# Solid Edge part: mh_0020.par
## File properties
Title: shaft
Author: edge
Template: normal.par
Last saved by: edge
Revision: 33
Application: Solid Edge
Material: SWM-B
非切断部品: False
文書内容のタイプ: 0
Density: 0.007850 g/mm^3
Accuracy: 0.99
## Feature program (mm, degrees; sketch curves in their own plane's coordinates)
sketch for "unnamed Protrusion 1" plane through (0, 0, 0) normal (1, 0, 0) x-axis (0, 1, 0)
  circle centre (0, 0) radius 1.5
extrude "unnamed Protrusion 1" add finite 15 symmetric
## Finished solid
Body 1: solid body, 3 faces, 2 edges, 0 vertices.
  Faces by surface: plane 2, cylinder 1
  Edges by curve: circle 2
Bounding box of the edges (mm): 15.000 x 3.000 x 3.000, from (-7.5, -1.5, -1.5) to (7.5, 1.5, 1.5).
Cylindrical faces by radius (mm): R1.5 x1
Planar faces by outward normal: +x 1, -x 1
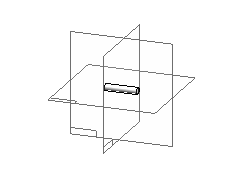
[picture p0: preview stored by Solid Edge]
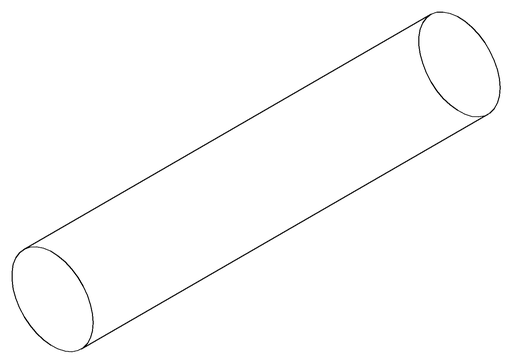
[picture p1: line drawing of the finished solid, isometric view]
